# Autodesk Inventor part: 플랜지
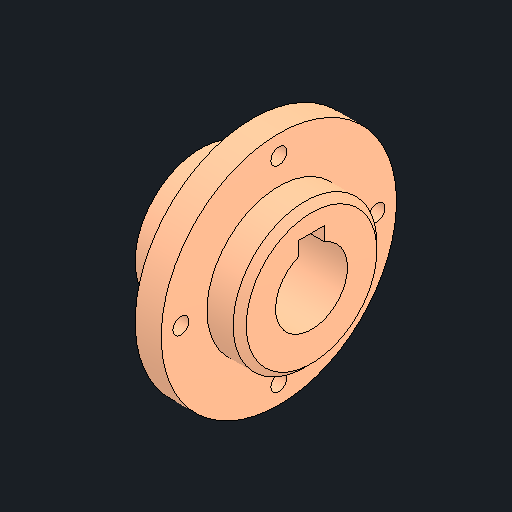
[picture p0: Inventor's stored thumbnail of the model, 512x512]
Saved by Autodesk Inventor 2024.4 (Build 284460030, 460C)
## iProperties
Created: 2026-08
Part Number: 플랜지
Material: 스테인리스강
Document SubType Name: Modeling
Designer: user
Density: 8.08 g/cm^3
Appearance: 기본값
Author: jhkim
Sending System: Autodesk Inventor 2027
Preprocessor: ST-DEVELOPER v20.1
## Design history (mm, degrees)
feature "솔리드1"
node "솔리드2"
